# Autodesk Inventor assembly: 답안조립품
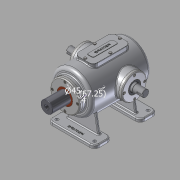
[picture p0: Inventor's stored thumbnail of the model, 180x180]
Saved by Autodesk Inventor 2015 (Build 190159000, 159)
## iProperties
Created: 2016-02
Part Number: 답안조립품
Document SubType Name: Assembly
Designer: Administrator
Mass: 7032.33 g
Surface Area: 4241.85 cm^2
Volume: 1855.5 cm^3
Density: 3.78999 g/cm^3
Author: Administrator
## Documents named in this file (15)
- C:\Users\Administrator\Desktop\360220V1001\답안조립품.iam
- C:\Users\Administrator\Desktop\360220V1001\본체.ipt
- C:\Users\Administrator\Desktop\360220V1001\축 커버.ipt
- C:\Users\Administrator\Desktop\360220V1001\슬라이드 커버.ipt
- C:\Users\Administrator\Desktop\360220V1001\볼트 M4x0.7.ipt
- C:\Users\Administrator\Desktop\360220V1001\오일실.ipt
- 오일실.ipt
- C:\Users\Administrator\Desktop\360220V1001\베어링 6205.ipt
- 베어링 6205.ipt
- C:\Users\Administrator\Desktop\360220V1001\부시.ipt
- C:\Users\Administrator\Desktop\360220V1001\편심축.ipt
- C:\Users\Administrator\Desktop\360220V1001\스프링.ipt
- C:\Users\Administrator\Desktop\360220V1001\슬라이드.ipt
- C:\Users\Administrator\Desktop\360220V1001\상부커버.ipt
- C:\Users\Administrator\Desktop\360220V1001\육각머리볼트 M4.ipt
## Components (12 placed, 1 different names)
1. M4x0.7:1
2. M4x0.7:4
3. M4x0.7:5
4. M4x0.7:6
5. M4x0.7:2
6. M4x0.7:7
7. M4x0.7:8
8. M4x0.7:9
9. M4x0.7:3
10. M4x0.7:10
11. M4x0.7:11
12. M4x0.7:12
